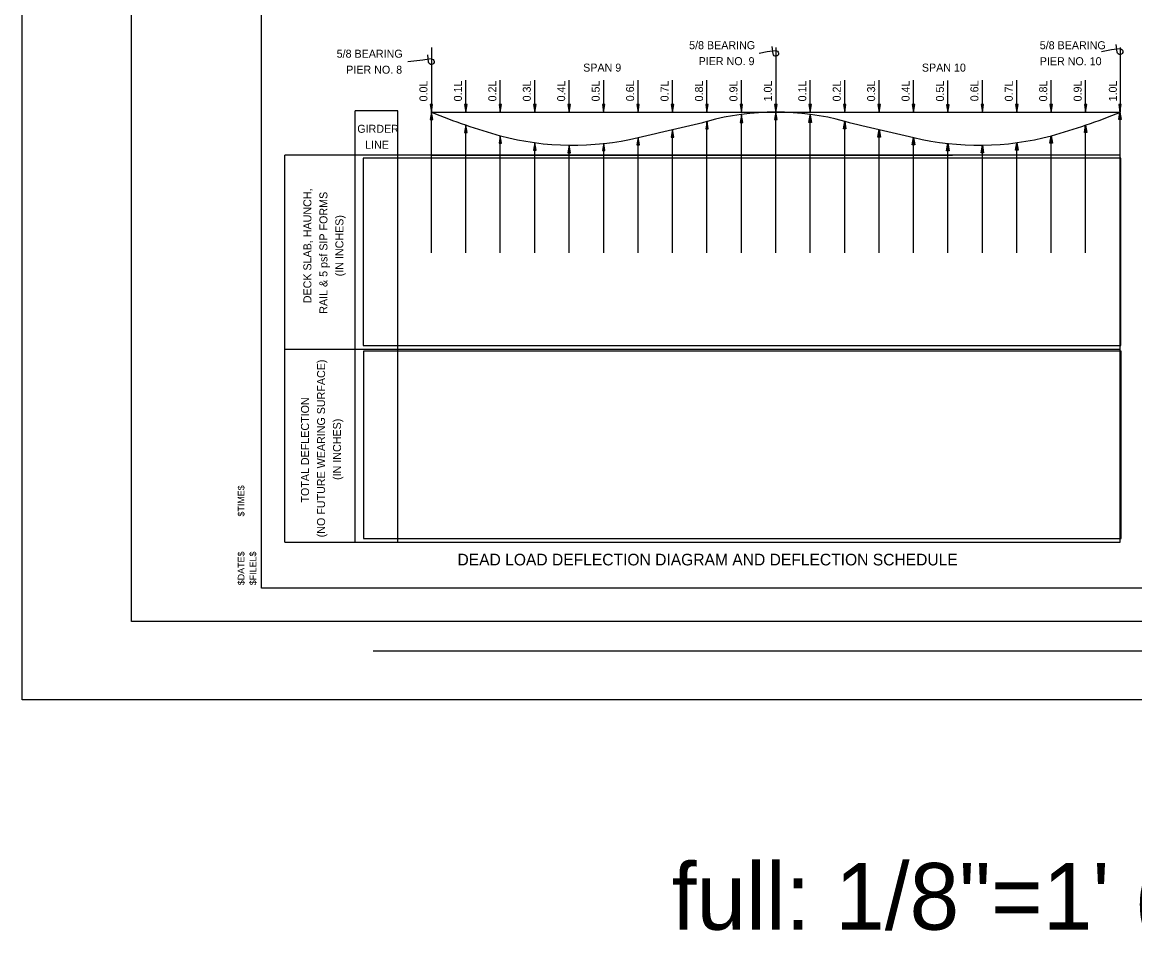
# Model space of a CAD drawing. Extents: x 4944 to 17449, y 3824 to 49087.
# Drawn here: x 12345 to 13947, y 29244 to 30579 of the extents above; entities that cross this region are included whole.
import ezdxf

# ---------------------------------------------------------------- set-up
doc = ezdxf.new("R2010")
doc.units = 0
for name, color, linetype in [('1', 7, 'Continuous'), ('37_S_TXT', 7, 'Continuous'), ('3A', 7, 'Continuous'), ('4', 7, 'Continuous'), ('6', 7, 'Continuous'), ('7', 7, 'Continuous'), ('BEAM', 7, 'Continuous'), ('DIM', 7, 'Continuous'), ('HATCH', 7, 'Continuous'), ('Level 14', 7, 'Continuous'), ('Level 25', 7, 'Continuous'), ('Level 34', 7, 'Continuous'), ('steel', 7, 'Continuous')]:
    doc.layers.add(name, color=color, linetype=linetype)

# ---------------------------------------------------------------- blocks, each defined once
blk = doc.blocks.new('STAMP_')
at = {"layer": 'steel'}
for s, p in [('$TIME$', (8.008, 7.429)), ('$DATE$', (8.008, 2.563)), ('$FILEL$', (8.846, 2.563))]:
    blk.add_text(s, height=0.4724, rotation=90, dxfattribs=at).set_placement(p)
blk = doc.blocks.new('DWG010')
at = {"layer": '1'}
for p, q in [((0, 0.047), (0.141, 0.047)), ((0.047, 0), (0.047, 0.125))]:
    blk.add_line(p, q, dxfattribs=at)
blk.add_arc((0, 0), 0.0469, 90, 0, dxfattribs=at)
blk = doc.blocks.new('ARROWH')
at = {"layer": '1'}
blk.add_lwpolyline([(0.123, -0.021), (0.123, 0.021), (-0.002, 0)], close=True, dxfattribs=at)

msp = doc.modelspace()

# ---------------------------------------------------------------- linework, layer by layer
at = {"layer": '37_S_TXT'}
msp.add_lwpolyline([(12345.1, 31907.7), (15801.2, 31907.7), (15801.2, 29603.7), (12345.1, 29603.7)], close=True, dxfattribs=at)
at = {"layer": '3A'}
for p, q in [((12934.2, 30542.9), (12934.2, 30449.8)), ((13430.1, 30542.9), (13430.1, 30449.8)), ((13925.6, 30542.9), (13925.6, 30449.8))]:
    msp.add_line(p, q, dxfattribs=at)
for points in [[(12835.8, 30113.8), (13926.7, 30113.8), (13926.7, 30383.6), (12835.8, 30383.6)], [(12836.4, 29836), (13927.3, 29836), (13927.3, 30105.8), (12836.4, 30105.8)]]:
    msp.add_lwpolyline(points, close=True, dxfattribs=at)
at = {"layer": '4'}
msp.add_line((12935.3, 30387.8), (13684.6, 30387.8), dxfattribs=at)
at = {"layer": '6'}
for p, q in [((13417.6, 30536.7), (13406.2, 30534)), ((13913.1, 30539.3), (13898.7, 30536.6)), ((12921.7, 30524.8), (12900.2, 30522.1)), ((12983.8, 30449.8), (12983.8, 30495.6)), ((13033.4, 30449.8), (13033.4, 30495.6)), ((13083, 30449.8), (13083, 30495.6)), ((13132.6, 30449.8), (13132.6, 30495.6)), ((13182.2, 30449.8), (13182.2, 30495.6)), ((13231.8, 30450), (13231.8, 30495.8)), ((13281.4, 30449.8), (13281.4, 30495.6)), ((13330.9, 30449.8), (13330.9, 30495.6)), ((13380.5, 30449.8), (13380.5, 30495.6)), ((13479.7, 30449.8), (13479.7, 30495.6)), ((13529.2, 30449.8), (13529.2, 30495.6)), ((13578.8, 30449.8), (13578.8, 30495.6)), ((13628.3, 30449.8), (13628.3, 30495.6)), ((13677.9, 30449.6), (13677.9, 30495.5)), ((13727.4, 30450), (13727.4, 30495.8)), ((13776.9, 30449.8), (13776.9, 30495.6)), ((13826.5, 30449.8), (13826.5, 30495.6)), ((13876, 30449.8), (13876, 30495.6)), ((12934.2, 30247), (12934.2, 30449.8)), ((12934.2, 30449.8), (12934.2, 30449.8)), ((12983.8, 30449.8), (12983.8, 30449.8)), ((13033.4, 30449.8), (13033.4, 30449.8)), ((13083, 30449.8), (13083, 30449.8)), ((13132.6, 30449.8), (13132.6, 30449.8)), ((13182.2, 30449.8), (13182.2, 30449.8)), ((13231.8, 30449.8), (13231.8, 30449.8)), ((13281.4, 30449.8), (13281.4, 30449.8)), ((13330.9, 30449.8), (13330.9, 30449.8)), ((13380.5, 30449.8), (13380.5, 30449.8)), ((13430.1, 30247), (13430.1, 30449.8)), ((13430.1, 30449.8), (13430.1, 30449.8)), ((13479.7, 30449.8), (13479.7, 30449.8)), ((13529.2, 30449.8), (13529.2, 30449.8)), ((13578.8, 30449.8), (13578.8, 30449.8)), ((13628.3, 30449.8), (13628.3, 30449.8)), ((13677.8, 30449.8), (13677.8, 30449.8)), ((13727.4, 30449.8), (13727.4, 30449.8)), ((13776.9, 30449.8), (13776.9, 30449.8)), ((13826.5, 30449.8), (13826.5, 30449.8)), ((13876, 30449.8), (13876, 30449.8)), ((13925.6, 29830.4), (13925.6, 30449.8)), ((13925.6, 30449.8), (13925.6, 30449.8)), ((12983.8, 30247), (12983.8, 30431.2)), ((13330.9, 30247), (13330.9, 30436.5)), ((13380.5, 30247), (13380.5, 30445.8)), ((13479.7, 30247), (13479.7, 30445.8)), ((13529.2, 30247), (13529.2, 30436.5)), ((13876, 30247), (13876, 30431.2)), ((13033.4, 30247), (13033.4, 30415.7)), ((13281.4, 30247), (13281.4, 30424.7)), ((13578.8, 30247), (13578.8, 30424.7)), ((13826.5, 30247), (13826.5, 30415.7)), ((13083, 30247), (13083, 30405.8)), ((13132.6, 30247), (13132.6, 30402.1)), ((13182.2, 30247.2), (13182.2, 30405)), ((13231.8, 30247), (13231.8, 30413.2)), ((13628.3, 30247), (13628.3, 30413.2)), ((13677.9, 30247), (13677.9, 30404.9)), ((13727.4, 30247), (13727.4, 30402.1)), ((13776.9, 30247), (13776.9, 30405.8))]:
    msp.add_line(p, q, dxfattribs=at)
at = {"layer": '7'}
for p, q in [((12934.2, 30449.8), (13430.1, 30449.8)), ((13430.1, 30449.8), (13925.6, 30449.8))]:
    msp.add_line(p, q, dxfattribs=at)
at = {"layer": 'BEAM'}
for centre, radius, start, end in [((13288.5, 31319), 938.7, 247.8233, 254.2284), ((13430.1, 30074.5), 375.3, 74.6834, 105.3166), ((13571.7, 31319), 938.7, 285.7716, 292.1767), ((11319.6, 38793.4), 8595.5, 282.85378, 283.53281), ((15540.7, 38793.4), 8595.5, 256.46719, 257.14622), ((13137.5, 30805), 402.9, 255.0329, 283.5345), ((13722.8, 30805), 402.9, 256.4655, 284.9671)]:
    msp.add_arc(centre, radius, start, end, dxfattribs=at)
at = {"layer": 'DIM'}
msp.add_lwpolyline([(12502.3, 31828.5), (15766.4, 31828.5), (15766.4, 29716.5), (12502.3, 29716.5)], close=True, dxfattribs=at)
at = {"layer": 'Level 14'}
msp.add_lwpolyline([(15713.6, 29764.5), (12689.5, 29764.5), (12689.5, 31780.5), (15713.6, 31780.5)], close=True, dxfattribs=at)
at = {"layer": 'Level 25'}
msp.add_line((12850.3, 29674.2), (15586.3, 29674.2), dxfattribs=at)
at = {"layer": 'Level 34'}
for p, q in [((12824.6, 29830.4), (12824.6, 30451.4)), ((12885.8, 30451.4), (12824.6, 30451.4)), ((12885.8, 29831.4), (12885.8, 30451.4)), ((12723.3, 29830.4), (12723.3, 30387.8)), ((13925.6, 30387.8), (12723.3, 30387.8)), ((12723.3, 30108.6), (13925.6, 30108.6)), ((12723.3, 29830.4), (13925.6, 29830.4))]:
    msp.add_line(p, q, dxfattribs=at)

# ---------------------------------------------------------------- block references
at = {"layer": '6'}
for name, p, xscale, yscale, rotation in [('DWG010', (13430.1, 30534.2), 85.92279574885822, -85.92279574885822, -172.86861111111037), ('DWG010', (13925.6, 30536.8), 85.92279574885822, -85.92279574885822, -172.8686111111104), ('DWG010', (12934.2, 30522.3), 85.92279574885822, -85.9227957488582, -172.86861111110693), ('ARROWH', (12934.2, 30450), 85.9227957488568, 85.9227957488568, 90), ('ARROWH', (12934.3, 30449.6), 85.92279574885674, 85.92279574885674, -90.00000000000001), ('ARROWH', (12983.8, 30450), 85.9227957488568, 85.9227957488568, 90), ('ARROWH', (13033.4, 30450), 85.9227957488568, 85.9227957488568, 90), ('ARROWH', (13083, 30450), 85.9227957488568, 85.9227957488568, 90), ('ARROWH', (13132.6, 30450), 85.9227957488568, 85.9227957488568, 90), ('ARROWH', (13182.1, 30450), 85.9227957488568, 85.9227957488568, 90), ('ARROWH', (13231.7, 30450.1), 85.9227957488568, 85.9227957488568, 90), ('ARROWH', (13281.3, 30450), 85.9227957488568, 85.9227957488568, 90), ('ARROWH', (13330.9, 30450), 85.9227957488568, 85.9227957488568, 90), ('ARROWH', (13380.5, 30450), 85.9227957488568, 85.9227957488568, 90), ('ARROWH', (13430.1, 30450), 85.9227957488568, 85.9227957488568, 90), ('ARROWH', (13430.1, 30449.6), 85.92279574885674, 85.92279574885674, -90.00000000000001), ('ARROWH', (13479.6, 30450), 85.9227957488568, 85.9227957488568, 90), ('ARROWH', (13529.2, 30450), 85.9227957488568, 85.9227957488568, 90), ('ARROWH', (13578.7, 30450), 85.9227957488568, 85.9227957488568, 90), ('ARROWH', (13628.3, 30450), 85.9227957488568, 85.9227957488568, 90), ('ARROWH', (13677.8, 30449.8), 85.9227957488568, 85.9227957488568, 90), ('ARROWH', (13727.4, 30450.1), 85.9227957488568, 85.9227957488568, 90), ('ARROWH', (13776.9, 30450), 85.9227957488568, 85.9227957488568, 90), ('ARROWH', (13826.5, 30450), 85.9227957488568, 85.9227957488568, 90), ('ARROWH', (13876, 30450), 85.9227957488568, 85.9227957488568, 90), ('ARROWH', (13925.5, 30450), 85.9227957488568, 85.9227957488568, 90), ('ARROWH', (13925.5, 30449.6), 85.92279574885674, -85.9227957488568, -90.00000000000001), ('ARROWH', (12983.8, 30431), 85.92279574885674, 85.92279574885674, -90.00000000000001), ('ARROWH', (13331, 30436.3), 85.92279574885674, 85.92279574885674, -90.00000000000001), ('ARROWH', (13380.6, 30445.4), 85.92279574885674, 85.92279574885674, -90.00000000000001), ('ARROWH', (13479.6, 30445.4), 85.92279574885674, -85.92279574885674, -90.00000000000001), ('ARROWH', (13529.2, 30436.3), 85.92279574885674, -85.92279574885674, -90.00000000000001), ('ARROWH', (13876, 30431), 85.92279574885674, -85.92279574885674, -90.00000000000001), ('ARROWH', (13033.4, 30415.5), 85.92279574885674, 85.92279574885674, -90.00000000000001), ('ARROWH', (13281.4, 30424.5), 85.92279574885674, 85.92279574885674, -90.00000000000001), ('ARROWH', (13578.7, 30424.5), 85.92279574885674, -85.92279574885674, -90.00000000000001), ('ARROWH', (13826.5, 30415.5), 85.92279574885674, -85.92279574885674, -90.00000000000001), ('ARROWH', (13083, 30405.6), 85.92279574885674, 85.92279574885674, -90.00000000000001), ('ARROWH', (13132.6, 30401.9), 85.92279574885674, 85.92279574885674, -90.00000000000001), ('ARROWH', (13182.2, 30404.9), 85.92279574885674, 85.92279574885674, -90.00000000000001), ('ARROWH', (13231.8, 30413.1), 85.92279574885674, 85.92279574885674, -90.00000000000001), ('ARROWH', (13628.3, 30413.1), 85.92279574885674, -85.92279574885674, -90.00000000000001), ('ARROWH', (13677.8, 30404.7), 85.92279574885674, -85.92279574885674, -90.00000000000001), ('ARROWH', (13727.4, 30401.9), 85.92279574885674, -85.92279574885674, -90.00000000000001), ('ARROWH', (13776.9, 30405.6), 85.92279574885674, -85.92279574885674, -90.00000000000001)]:
    msp.add_blockref(name, p, dxfattribs=dict(at, xscale=xscale, yscale=yscale, rotation=rotation))
at = {"layer": 'steel', "xscale": 20.320040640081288, "yscale": 20.320040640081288}
msp.add_blockref('STAMP_', (12502.3, 29716.5), dxfattribs=at)

# ---------------------------------------------------------------- texts
at = {"layer": '3A'}
for s, p in [('5/8 BEARING ', (13305.2, 30540.4)), ('5/8 BEARING ', (13810, 30540.3)), ('5/8 BEARING ', (12797.8, 30528.1)), ('PIER NO. 9', (13318.9, 30517.4)), ('PIER NO. 10', (13810, 30517.3)), ('PIER NO. 8', (12811.6, 30505.1)), ('SPAN 9', (13152.7, 30508.1)), ('SPAN 10', (13640.3, 30508.1)), ('GIRDER', (12827.5, 30420)), ('LINE', (12838.8, 30397))]:
    msp.add_text(s, height=11.52, dxfattribs=at).set_placement(p)
for s, p in [('0.0L', (12928.5, 30465.2)), ('0.1L', (12978.1, 30465.2)), ('0.2L', (13027.7, 30465.2)), ('0.3L', (13077.3, 30465.2)), ('0.4L', (13126.8, 30465.2)), ('0.5L', (13176.4, 30465.2)), ('0.6L', (13226, 30465.4)), ('0.7L', (13275.6, 30465.2)), ('0.8L', (13325.2, 30465.2)), ('0.9L', (13374.8, 30465.2)), ('1.0L', (13424.3, 30465.2)), ('0.1L', (13473.9, 30465.2)), ('0.2L', (13523.5, 30465.2)), ('0.3L', (13573, 30465.2)), ('0.4L', (13622.6, 30465.2)), ('0.5L', (13672.1, 30465.1)), ('0.6L', (13721.7, 30465.4)), ('0.7L', (13771.2, 30465.2)), ('0.8L', (13820.7, 30465.2)), ('0.9L', (13870.3, 30465.2)), ('1.0L', (13921, 30465.2)), ('DECK SLAB, HAUNCH,', (12761.4, 30174.6)), ('RAIL & 5 psf SIP FORMS', (12784.5, 30159.5)), ('(IN INCHES)', (12807.5, 30213.4)), ('(NO FUTURE WEARING SURFACE)', (12781.1, 29837.6)), ('TOTAL DEFLECTION', (12758, 29887.6)), ('(IN INCHES)', (12804.1, 29920.2))]:
    msp.add_text(s, height=11.52, rotation=90, dxfattribs=at).set_placement(p)
at = {"layer": 'BEAM'}
msp.add_text('DEAD LOAD DEFLECTION DIAGRAM AND DEFLECTION SCHEDULE', height=16.8, dxfattribs=at).set_placement((12971.7, 29797.1))
at = {"layer": 'HATCH'}
msp.add_text('full: 1/8"=1\' (1=8) (96)', height=96, dxfattribs=at).set_placement((13280.1, 29272.6))

doc.saveas('drawing.dxf')
